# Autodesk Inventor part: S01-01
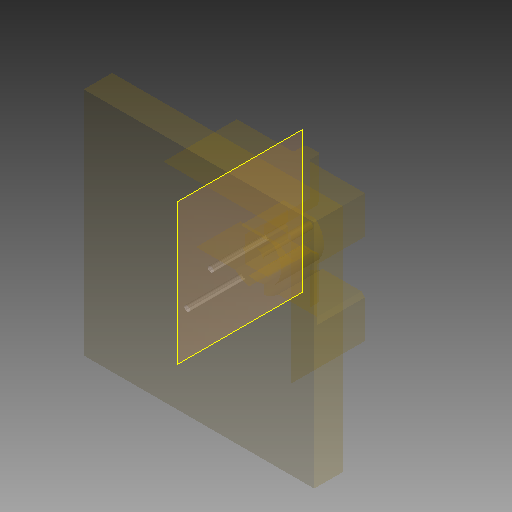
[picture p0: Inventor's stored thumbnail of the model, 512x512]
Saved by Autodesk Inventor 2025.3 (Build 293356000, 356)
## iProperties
Part Number: S01-01
Material: Generický
Document SubType Name: Modelování
Designer: Patrik
Appearance: Výchozí
Mass: 69.9896 g
Surface Area: 141.247 cm^2
Volume: 69.9896 cm^3
Density: 1 g/cm^3
Description: Tvárnice
Author: Patrik
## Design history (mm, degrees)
node "Sestava - mold design_MODEL - mk4 Blenddoor Tab v4_2_CV_Base"
node "Pracovní rovina1"
feature "Vyřezání8"
node "Objemová tělesa"
node "Povrchová tělesa"
feature "Těleso8::Sestava - mold design_MODEL - mk4 Blenddoor Tab v4_"
tag "Prvek štítků1"
node "Těleso8"
feature "Sestava - mold design_MODEL - mk4 Blenddoor Tab v4_2_CV_Base"
feature "Plocha10"
node "Povrch10"
